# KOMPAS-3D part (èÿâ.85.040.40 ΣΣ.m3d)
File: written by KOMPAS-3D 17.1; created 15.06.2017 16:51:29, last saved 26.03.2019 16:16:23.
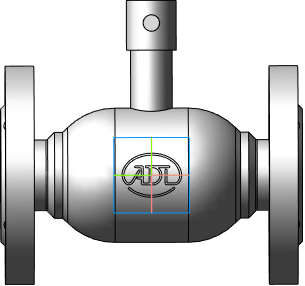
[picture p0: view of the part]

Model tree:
1. Операция без истории:2  (labels: Сталь 20  ГОСТ 1050-88)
